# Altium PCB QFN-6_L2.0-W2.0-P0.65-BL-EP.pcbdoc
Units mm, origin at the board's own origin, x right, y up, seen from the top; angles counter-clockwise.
Board outline 15.1 x 15.9 mm, 2 copper layers (Top Layer, Bottom Layer), stack 0 mm thick; 1 components, 0 nets, 7 pads, 0 vias.
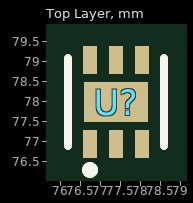
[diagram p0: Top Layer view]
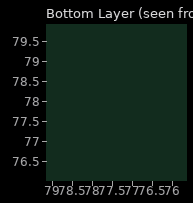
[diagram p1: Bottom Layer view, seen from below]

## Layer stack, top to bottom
Top Layer: signal copper (thickness not stored)
Bottom Layer: signal copper (thickness not stored)

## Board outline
84.95,69.85 69.85,69.85 69.85,85.75 84.95,85.75

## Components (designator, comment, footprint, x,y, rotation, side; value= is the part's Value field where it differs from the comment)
U? "" QFN-6_L2.0-W2.0-P0.65-BL-EP 77.4,78 r0 top

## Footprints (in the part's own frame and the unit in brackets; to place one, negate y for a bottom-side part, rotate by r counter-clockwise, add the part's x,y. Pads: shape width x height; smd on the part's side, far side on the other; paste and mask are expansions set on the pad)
QFN-6_L2.0-W2.0-P0.65-BL-EP [mm]
  rect 0.35x0.7 smd paste+0 mask+0.05: 1(-0.65,-1.05) 2(0,-1.05) 3(0.65,-1.05) 4(0.65,1.05) 5(0,1.05) 6(-0.65,1.05)
  rect 1.6x1 smd: 7(0,0)
  silkscreen extent -1.2,-1.8 1.2,1.1

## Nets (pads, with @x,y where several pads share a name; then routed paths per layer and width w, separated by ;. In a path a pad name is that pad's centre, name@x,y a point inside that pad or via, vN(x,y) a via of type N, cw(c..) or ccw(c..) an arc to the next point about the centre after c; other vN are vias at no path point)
pads on no net: U?.1 U?.2 U?.3 U?.4 U?.5 U?.6 U?.7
